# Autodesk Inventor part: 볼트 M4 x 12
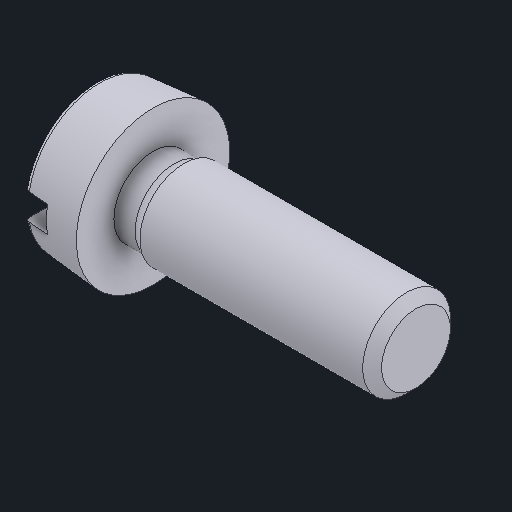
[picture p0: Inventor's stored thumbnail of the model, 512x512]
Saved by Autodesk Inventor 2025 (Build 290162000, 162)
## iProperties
Created: 2025-08
Part Number: 볼트 M4 x 12
Material: 강철, 연강
Description: 6각머리 태핑 나사
Document SubType Name: Modeling
Designer: infra10
Density: 7.85 g/cm^3
Appearance: 기본값
Author: jhkim
Sending System: Autodesk Inventor 2026
Preprocessor: ST-DEVELOPER v20.1
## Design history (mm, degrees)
feature "Solid1"
node "솔리드1"
